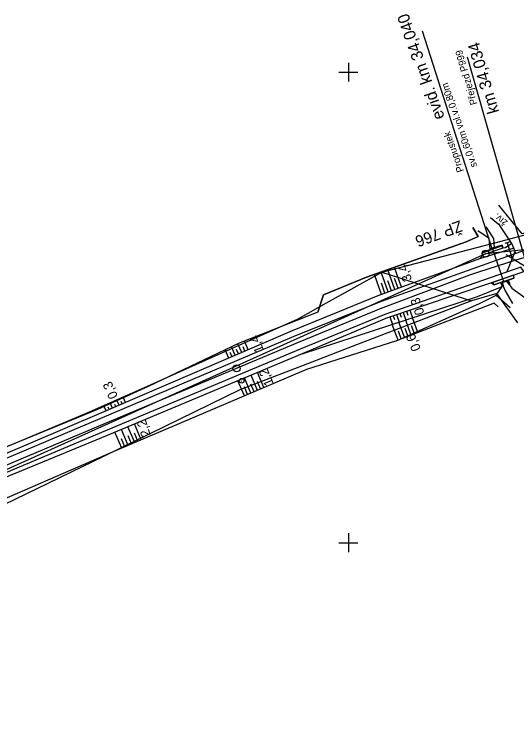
# Model space of a CAD drawing. Extents: x -805730 to -804640, y -1150889 to -1150366.
# Drawn here: x -804971 to -804864.2, y -1150637.9 to -1150487.7 of the extents above; entities that cross this region are included whole.
import ezdxf

# ---------------------------------------------------------------- set-up
doc = ezdxf.new("R2010")
doc.units = 0
for name, color, linetype in [('0381KM032-037P - Vrstva 1', 7, 'Continuous'), ('0381KM032-037P - Vrstva 17', 7, 'Continuous'), ('0381KM032-037P - Vrstva 19', 7, 'Continuous'), ('0381KM032-037P - Vrstva 4', 7, 'Continuous'), ('0381KM032-037P - Vrstva 48', 7, 'Continuous'), ('0381KM032-037P - Vrstva 49', 7, 'Continuous'), ('0381KM032-037P - Vrstva 51', 7, 'Continuous'), ('0381KM032-037P - Vrstva 55', 7, 'Continuous'), ('0381KM032-037P - Vrstva 7', 7, 'Continuous'), ('hran DP - hran DP', 7, 'Continuous'), ('krizky_1000 - Vrstva 1', 7, 'Continuous'), ('vyt_sit - ohrožené', 7, 'Continuous'), ('vyt_sit - polygon', 7, 'Continuous')]:
    doc.layers.add(name, color=color, linetype=linetype)

msp = doc.modelspace()

# ---------------------------------------------------------------- linework, layer by layer
at = {"layer": '0381KM032-037P - Vrstva 1'}
for points in [[(-804836.89, -1150533.13), (-804845.84, -1150535.01), (-804855.06, -1150537.3), (-804860.78, -1150538.93), (-804864.46, -1150539.98), (-804872.35, -1150542.54)], [(-804872.35, -1150542.54), (-804874.25, -1150543.16), (-804893.23, -1150550.28), (-804910.33, -1150557.31)], [(-804910.33, -1150557.31), (-804952.12, -1150574.92), (-804994.42, -1150592.71), (-805038.63, -1150611.27), (-805057.71, -1150619.3), (-805074.24, -1150626.27)]]:
    msp.add_lwpolyline(points, dxfattribs=at)
at = {"layer": '0381KM032-037P - Vrstva 17'}
for p, q in [((-804873.58, -1150533.02), (-804873.58, -1150533.02)), ((-804867.35, -1150536.9), (-804871.44, -1150538.39))]:
    msp.add_line(p, q, dxfattribs=at)
for points in [[(-804734.71, -1150510.96), (-804735.96, -1150513.84), (-804741.77, -1150514.83), (-804760.36, -1150517.2), (-804795.4, -1150521.06), (-804816.51, -1150523.78), (-804835.4, -1150526.88), (-804850, -1150530.66), (-804863.08, -1150534.36), (-804866.23, -1150530.55), (-804868.05, -1150528.28)], [(-804873.58, -1150533.02), (-804872.42, -1150534.97), (-804875, -1150536.1), (-804896.18, -1150543.61), (-804905.28, -1150547.35), (-804906.51, -1150551)], [(-804868.16, -1150549.89), (-804869.02, -1150549.09), (-804889.78, -1150557.12), (-804908.89, -1150563.18), (-804949.8, -1150580.61), (-804991.45, -1150598.69), (-805036.34, -1150617.58)], [(-804906.51, -1150551), (-804923.2, -1150557.6), (-804942.52, -1150566.83), (-804953.3, -1150571.71), (-804995.99, -1150589.23), (-805040.03, -1150605.68), (-805044.15, -1150607.13)]]:
    msp.add_lwpolyline(points, dxfattribs=at)
at = {"layer": '0381KM032-037P - Vrstva 19'}
for p, q in [((-804869.43, -1150537.57), (-804884.27, -1150491.28)), ((-804867.32, -1150536.83), (-804871.54, -1150538.31)), ((-804866.95, -1150544.56), (-804869.42, -1150537.44)), ((-804867.2, -1150537.4), (-804867.36, -1150536.8)), ((-804871.36, -1150538.86), (-804871.49, -1150538.28)), ((-804864.83, -1150543.77), (-804869.08, -1150545.22)), ((-804869.27, -1150544.65), (-804869.59, -1150544.8)), ((-804869.59, -1150544.8), (-804869.04, -1150545.2)), ((-804867.71, -1150544.71), (-804867.31, -1150545.53))]:
    msp.add_line(p, q, dxfattribs=at)
for points in [[(-804871.36, -1150538.86), (-804871.54, -1150538.31), (-804867.32, -1150536.83), (-804867.2, -1150537.4), (-804871.36, -1150538.86)], [(-804871.54, -1150538.31), (-804871.54, -1150538.31), (-804871.49, -1150538.28), (-804869.89, -1150537.71)], [(-804869.89, -1150537.71), (-804869.42, -1150537.44), (-804868.94, -1150537.26)], [(-804867.32, -1150536.83), (-804867.32, -1150536.83), (-804867.36, -1150536.8), (-804868.94, -1150537.26)], [(-804865.03, -1150543.19), (-804864.83, -1150543.77), (-804869.08, -1150545.22), (-804869.27, -1150544.65), (-804865.03, -1150543.19)], [(-804866.16, -1150544.27), (-804864.91, -1150543.76), (-804864.83, -1150543.77), (-804864.83, -1150543.77)], [(-804865.03, -1150543.19), (-804864.94, -1150543.15), (-804864.91, -1150543.76)], [(-804869.08, -1150545.22), (-804869.08, -1150545.22), (-804869.04, -1150545.2), (-804867.71, -1150544.71), (-804867.33, -1150544.58)], [(-804867.33, -1150544.58), (-804867.03, -1150545.63), (-804867.31, -1150545.53)]]:
    msp.add_lwpolyline(points, dxfattribs=at)
msp.add_lwpolyline([(-804866.45, -1150544.36), (-804866.16, -1150544.27), (-804865.77, -1150544.86), (-804865.78, -1150545.2)], close=True, dxfattribs=at)
for centre, major_axis, ratio in [((-804869.43, -1150537.43), (-0.407, -0.192), 0.02514), ((-804866.89, -1150544.48), (0.45, 0.118), 0.13222)]:
    msp.add_ellipse(centre, major_axis=major_axis, ratio=ratio, dxfattribs=at)
at = {"layer": '0381KM032-037P - Vrstva 4'}
for p, q in [((-804874.8, -1150496.75), (-804862.62, -1150539.46)), ((-804865.82, -1150536.14), (-804866.77, -1150536.45)), ((-804866.3, -1150536.29), (-804865.21, -1150539.62)), ((-804862.58, -1150541.24), (-804866.52, -1150538.84)), ((-804864.62, -1150538.22), (-804866.38, -1150542.48))]:
    msp.add_line(p, q, dxfattribs=at)
for points in [[(-804864.42, -1150538.53), (-804864.84, -1150537.45), (-804872.17, -1150539.66)], [(-804864.42, -1150538.53), (-804893.06, -1150548.77), (-804911.6, -1150556.2), (-804952.82, -1150573.68), (-804994.86, -1150591.44), (-805039.39, -1150610.13), (-805056.71, -1150617.44), (-805097.6, -1150634.39)], [(-804872.17, -1150539.66), (-804893.72, -1150547.52), (-804911.96, -1150555), (-804952.93, -1150572.63), (-804995.29, -1150590.69), (-805039.86, -1150609.18), (-805057.83, -1150616.69), (-805068.36, -1150621.07), (-805097.92, -1150633.57)], [(-804862.73, -1150542.41), (-804863.39, -1150541.46), (-804892.29, -1150551.48), (-804910.22, -1150558.86), (-804951.61, -1150576.23), (-804993.7, -1150593.96), (-805038.63, -1150612.92), (-805049.62, -1150617.53), (-805055.59, -1150619.94), (-805066.74, -1150624.75), (-805096.44, -1150637.01)], [(-804864.94, -1150543.15), (-804869.59, -1150544.8), (-804891.93, -1150552.26), (-804909.8, -1150559.87), (-804951.24, -1150577.2), (-804993.38, -1150594.6), (-805038.39, -1150613.8), (-805059.54, -1150622.79), (-805066.49, -1150625.57), (-805096.25, -1150637.87)], [(-804864.94, -1150543.15), (-804862.73, -1150542.41), (-804862.73, -1150542.41)]]:
    msp.add_lwpolyline(points, dxfattribs=at)
at = {"layer": '0381KM032-037P - Vrstva 48'}
for p, q in [((-804890.12, -1150546.21), (-804891.64, -1150542)), ((-804888.71, -1150545.7), (-804890.22, -1150541.5)), ((-804892.94, -1150547.24), (-804894.46, -1150543.01)), ((-804891.53, -1150546.73), (-804893.05, -1150542.5)), ((-804889.42, -1150545.95), (-804890.17, -1150543.85)), ((-804892.24, -1150546.98), (-804893, -1150544.87)), ((-804890.83, -1150546.47), (-804891.59, -1150544.36)), ((-804889.06, -1150551.3), (-804888.79, -1150552.11)), ((-804888.35, -1150551.06), (-804887.81, -1150552.69)), ((-804887.64, -1150550.83), (-804887.36, -1150551.65)), ((-804886.92, -1150550.59), (-804886.38, -1150552.23)), ((-804891.19, -1150552.02), (-804890.66, -1150553.62)), ((-804890.48, -1150551.78), (-804890.21, -1150552.58)), ((-804889.77, -1150551.54), (-804889.23, -1150553.16)), ((-804886.72, -1150555.74), (-804887.83, -1150552.7)), ((-804885.35, -1150555.12), (-804886.41, -1150552.24)), ((-804889.46, -1150556.98), (-804890.69, -1150553.63)), ((-804888.09, -1150556.36), (-804889.26, -1150553.17)), ((-804886.03, -1150555.43), (-804886.58, -1150553.95)), ((-804888.78, -1150556.67), (-804889.37, -1150555.03)), ((-804887.4, -1150556.05), (-804887.97, -1150554.49)), ((-804921.28, -1150559.01), (-804922.05, -1150557.14)), ((-804924.01, -1150560.18), (-804924.82, -1150558.38)), ((-804922.63, -1150559.59), (-804923.47, -1150557.73)), ((-804921.97, -1150559.3), (-804922.36, -1150558.36)), ((-804925.38, -1150560.77), (-804926.18, -1150559.02)), ((-804924.69, -1150560.48), (-804925.1, -1150559.59)), ((-804923.32, -1150559.88), (-804923.73, -1150558.97)), ((-804919.33, -1150567.63), (-804920.68, -1150564.42)), ((-804917.95, -1150567.04), (-804919.3, -1150563.84)), ((-804922.08, -1150568.8), (-804923.45, -1150565.58)), ((-804920.71, -1150568.22), (-804922.06, -1150565)), ((-804920.02, -1150567.92), (-804920.69, -1150566.31)), ((-804918.64, -1150567.33), (-804919.31, -1150565.73)), ((-804921.4, -1150568.51), (-804922.08, -1150566.9)), ((-804947.33, -1150570.22), (-804947.78, -1150569.21)), ((-804950.09, -1150571.4), (-804950.51, -1150570.45)), ((-804949.4, -1150571.11), (-804949.61, -1150570.62)), ((-804948.71, -1150570.81), (-804949.14, -1150569.83)), ((-804948.02, -1150570.52), (-804948.24, -1150570.02)), ((-804951.47, -1150572), (-804951.88, -1150571.07)), ((-804950.78, -1150571.7), (-804950.99, -1150571.23)), ((-804945.38, -1150578.73), (-804946.81, -1150575.35)), ((-804944, -1150578.14), (-804945.43, -1150574.77)), ((-804948.14, -1150579.91), (-804949.58, -1150576.51)), ((-804946.76, -1150579.32), (-804948.19, -1150575.93)), ((-804944.69, -1150578.44), (-804945.4, -1150576.75)), ((-804947.45, -1150579.61), (-804948.17, -1150577.92)), ((-804946.07, -1150579.03), (-804946.79, -1150577.33))]:
    msp.add_line(p, q, dxfattribs=at)
at = {"layer": '0381KM032-037P - Vrstva 49'}
for p, q in [((-804867.85, -1150532.57), (-804869.83, -1150530.99)), ((-804872.42, -1150534.97), (-804873.58, -1150533.02)), ((-804865.31, -1150536.46), (-804867.85, -1150532.57)), ((-804867.03, -1150545.63), (-804867.33, -1150544.58)), ((-804865.78, -1150545.2), (-804866.45, -1150544.36)), ((-804868.59, -1150547.42), (-804865.62, -1150550.04))]:
    msp.add_line(p, q, dxfattribs=at)
for points in [[(-804868.94, -1150537.26), (-804869.09, -1150535.33), (-804870.73, -1150532.86)], [(-804869.89, -1150537.71), (-804870.12, -1150535.33), (-804872.5, -1150533.72)], [(-804906.51, -1150551), (-804905.28, -1150547.35), (-804896.18, -1150543.61), (-804875, -1150536.1), (-804872.42, -1150534.97)], [(-804871.36, -1150538.86), (-804871.49, -1150538.28), (-804869.89, -1150537.71)], [(-804865.31, -1150536.46), (-804866.66, -1150537.33), (-804867.2, -1150537.4), (-804871.36, -1150538.86)], [(-804868.94, -1150537.26), (-804867.36, -1150536.8), (-804867.2, -1150537.4)], [(-804871.36, -1150538.86), (-804872.17, -1150539.66), (-804893.72, -1150547.52), (-804911.96, -1150555), (-804952.93, -1150572.63), (-804995.29, -1150590.69), (-805039.86, -1150609.18), (-805057.83, -1150616.69), (-805068.36, -1150621.07), (-805097.92, -1150633.57)], [(-804869.27, -1150544.65), (-804865.03, -1150543.19), (-804864.94, -1150543.15), (-804862.73, -1150542.41)], [(-804869.27, -1150544.65), (-804869.59, -1150544.8), (-804891.93, -1150552.26), (-804909.8, -1150559.87)], [(-804865.78, -1150545.2), (-804865.26, -1150545.89), (-804862.25, -1150548.13)], [(-804909.8, -1150559.87), (-804872.57, -1150547.72), (-804867.31, -1150545.53)], [(-804889.78, -1150557.12), (-804872.12, -1150549.16), (-804868.59, -1150547.42), (-804867.31, -1150545.53)], [(-804867.03, -1150545.63), (-804866.68, -1150546.48), (-804865.14, -1150549.2)], [(-804906.51, -1150551), (-804923.2, -1150557.6), (-804942.52, -1150566.83), (-804953.3, -1150571.71), (-804995.99, -1150589.23), (-805040.03, -1150605.68), (-805044.15, -1150607.13)], [(-804889.78, -1150557.12), (-804908.89, -1150563.18), (-804949.8, -1150580.61), (-804991.45, -1150598.69), (-805036.34, -1150617.58)], [(-804909.8, -1150559.87), (-804951.24, -1150577.2), (-804993.38, -1150594.6), (-805038.39, -1150613.8), (-805050.01, -1150619.25), (-805055.21, -1150621.51), (-805059.54, -1150622.79), (-805066.49, -1150625.57), (-805096.25, -1150637.87)]]:
    msp.add_lwpolyline(points, dxfattribs=at)
msp.add_ellipse((-804866.89, -1150544.48), major_axis=(0.45, 0.118), ratio=0.13222, start_param=2.866376, end_param=6.348957, dxfattribs=at)
at = {"layer": '0381KM032-037P - Vrstva 51'}
msp.add_line((-804867.85, -1150532.57), (-804869.83, -1150530.99), dxfattribs=at)
for points in [[(-804864.84, -1150537.45), (-804865.31, -1150536.46), (-804867.85, -1150532.57)], [(-804861.98, -1150536.58), (-804861.64, -1150537.54), (-804864.42, -1150538.53), (-804864.84, -1150537.45)]]:
    msp.add_lwpolyline(points, dxfattribs=at)
at = {"layer": '0381KM032-037P - Vrstva 55'}
msp.add_line((-804892.91, -1150542.49), (-804873.83, -1150548.59), dxfattribs=at)
at = {"layer": '0381KM032-037P - Vrstva 7'}
msp.add_line((-804922.71, -1150565.59), (-804922.61, -1150565.59), dxfattribs=at)
for centre, radius in [((-804923.76, -1150562.97), 0.75), ((-804922.66, -1150565.59), 0.5)]:
    msp.add_circle(centre, radius, dxfattribs=at)
at = {"layer": 'hran DP - hran DP'}
for p, q in [((-804868.93, -1150536.25), (-804855.75, -1150532.82)), ((-804892.91, -1150542.49), (-804868.93, -1150536.25)), ((-804904.62, -1150549.05), (-804892.91, -1150542.49)), ((-804868.47, -1150547.08), (-804873.83, -1150548.59)), ((-804864.02, -1150553.26), (-804868.47, -1150547.08)), ((-804910.68, -1150552.45), (-804904.62, -1150549.05)), ((-804873.83, -1150548.59), (-804889.79, -1150554.73)), ((-804919.88, -1150556.55), (-804910.68, -1150552.45)), ((-804889.79, -1150554.73), (-804898.28, -1150557.99)), ((-804930.31, -1150561.21), (-804919.88, -1150556.55)), ((-804898.28, -1150557.99), (-804902.34, -1150559.55)), ((-804902.34, -1150559.55), (-804906.85, -1150561.29)), ((-804942.65, -1150566.71), (-804930.31, -1150561.21)), ((-804906.85, -1150561.29), (-804923.02, -1150567.51)), ((-804954.99, -1150572.21), (-804942.65, -1150566.71)), ((-804923.02, -1150567.51), (-804951.89, -1150581.61)), ((-804956.48, -1150572.84), (-804954.99, -1150572.21)), ((-804968.41, -1150577.86), (-804956.48, -1150572.84)), ((-804981, -1150583.16), (-804968.41, -1150577.86)), ((-804951.89, -1150581.61), (-804973.16, -1150591.99))]:
    msp.add_line(p, q, dxfattribs=at)
at = {"layer": 'krizky_1000 - Vrstva 1'}
for points in [[(-804900, -1150498), (-804900, -1150502)], [(-804902, -1150500), (-804898, -1150500)], [(-804900, -1150598), (-804900, -1150602)], [(-804902, -1150600), (-804898, -1150600)]]:
    msp.add_lwpolyline(points, dxfattribs=at)
at = {"layer": 'vyt_sit - ohrožené'}
msp.add_line((-804870.89, -1150538.58), (-804870.79, -1150538.58), dxfattribs=at)
msp.add_circle((-804870.84, -1150538.58), 0.756, dxfattribs=at)
at = {"layer": 'vyt_sit - polygon'}
for p, q in [((-804870.84, -1150538.58), (-804740.83, -1150524.99)), ((-805047.55, -1150618.19), (-804870.84, -1150538.58))]:
    msp.add_line(p, q, dxfattribs=at)

# ---------------------------------------------------------------- texts
at = {"layer": '0381KM032-037P - Vrstva 19'}
for s, height, rotation, p in [('evid. km 34,040', 2.5, 109.3587, (-804879.52, -1150509.62)), ('sv.0,60m vol.v.0,80m', 1.5, 109.4315, (-804872.62, -1150520)), ('Propustek', 1.5, 109.4315, (-804875.45, -1150521))]:
    msp.add_text(s, height=height, rotation=rotation, dxfattribs=at).set_placement(p)
at = {"layer": '0381KM032-037P - Vrstva 4'}
for s, height, rotation, p in [('km 34,034', 2.5, 106.0257, (-804867.97, -1150508.45)), ('Přejezd P999', 1.5, 105.8715, (-804872.6, -1150506.75))]:
    msp.add_text(s, height=height, rotation=rotation, dxfattribs=at).set_placement(p)
at = {"layer": '0381KM032-037P - Vrstva 48'}
for s, rotation, p in [('3,4', 110.0448, (-804886.43, -1150544.12)), ('0,3', 108.4626, (-804883.82, -1150551.25)), ('0,6', 113.0694, (-804884.56, -1150558.81)), ('1,4', 111.5655, (-804917.87, -1150559.18)), ('1,2', 112.6972, (-804915.82, -1150566.2)), ('0,3', 114.3346, (-804948.89, -1150568.92)), ('2,2', 107.6972, (-804941.96, -1150577.16))]:
    msp.add_text(s, height=2, rotation=rotation, dxfattribs=at).set_placement(p)
at = {"layer": '0381KM032-037P - Vrstva 51'}
msp.add_text('živ.', height=1.5, rotation=141.4462, dxfattribs=at).set_placement((-804866.05, -1150531.74))
at = {"layer": 'vyt_sit - ohrožené'}
msp.add_text('ŽP 766', height=2.4, rotation=200, dxfattribs=at).set_placement((-804876.31, -1150531.46))

doc.saveas('drawing.dxf')
